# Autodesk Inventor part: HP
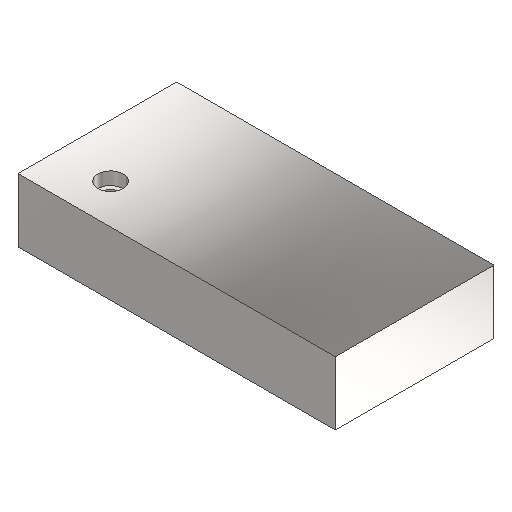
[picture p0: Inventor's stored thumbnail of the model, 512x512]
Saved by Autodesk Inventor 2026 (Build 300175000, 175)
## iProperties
Created: 2004-10
Part Number: HP
Document SubType Name: Modeling
Designer: Lars Bertram Pedersen
Manufacturer: Standard
Standards Organization: Custom
Material: Steel, Mild
Density: 7.85 g/cm^3
Appearance: Semi-Polished
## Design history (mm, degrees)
sketch "Sketch1"
  geometry: L1 (0, 0)-(100, 0); L2 (100, 0)-(100, 50); L3 (100, 50)-(0, 50); L4 (0, 50)-(0, 0); 1 further point
  constraints: 8 end point, 2 parallel, 1 coincident, 1 horizontal, 1 perpendicular
  dimensions: "d0" = 50 distance of L1.end L2.end; "d1" = 100 distance of L1.start L1.end
extrude "Extrusion1" new body sketch "Sketch1" distance "d2" = 20; taper "d3" = 0 deg
sketch "Sketch3"
  geometry: L1 (0, 0)-(0, 50) reference; L2 (100, 0)-(0, 0) reference; 2 further points
  dimensions: "d11" = 12.5 distance from line of L2 point (16.667, 12.5); "d12" = 16.667 distance from line of L1 point (16.667, 12.5)
hole "Hole1" sketch "Sketch3" diameter "d13" = 5; stored, may be unused: countersink angle "d17" = 90 deg, drill point angle "d19" = 118 deg; dims "d14" = 6, "d15" = 8, "d16" = 4, "d18" = 15
body "Solid1"
